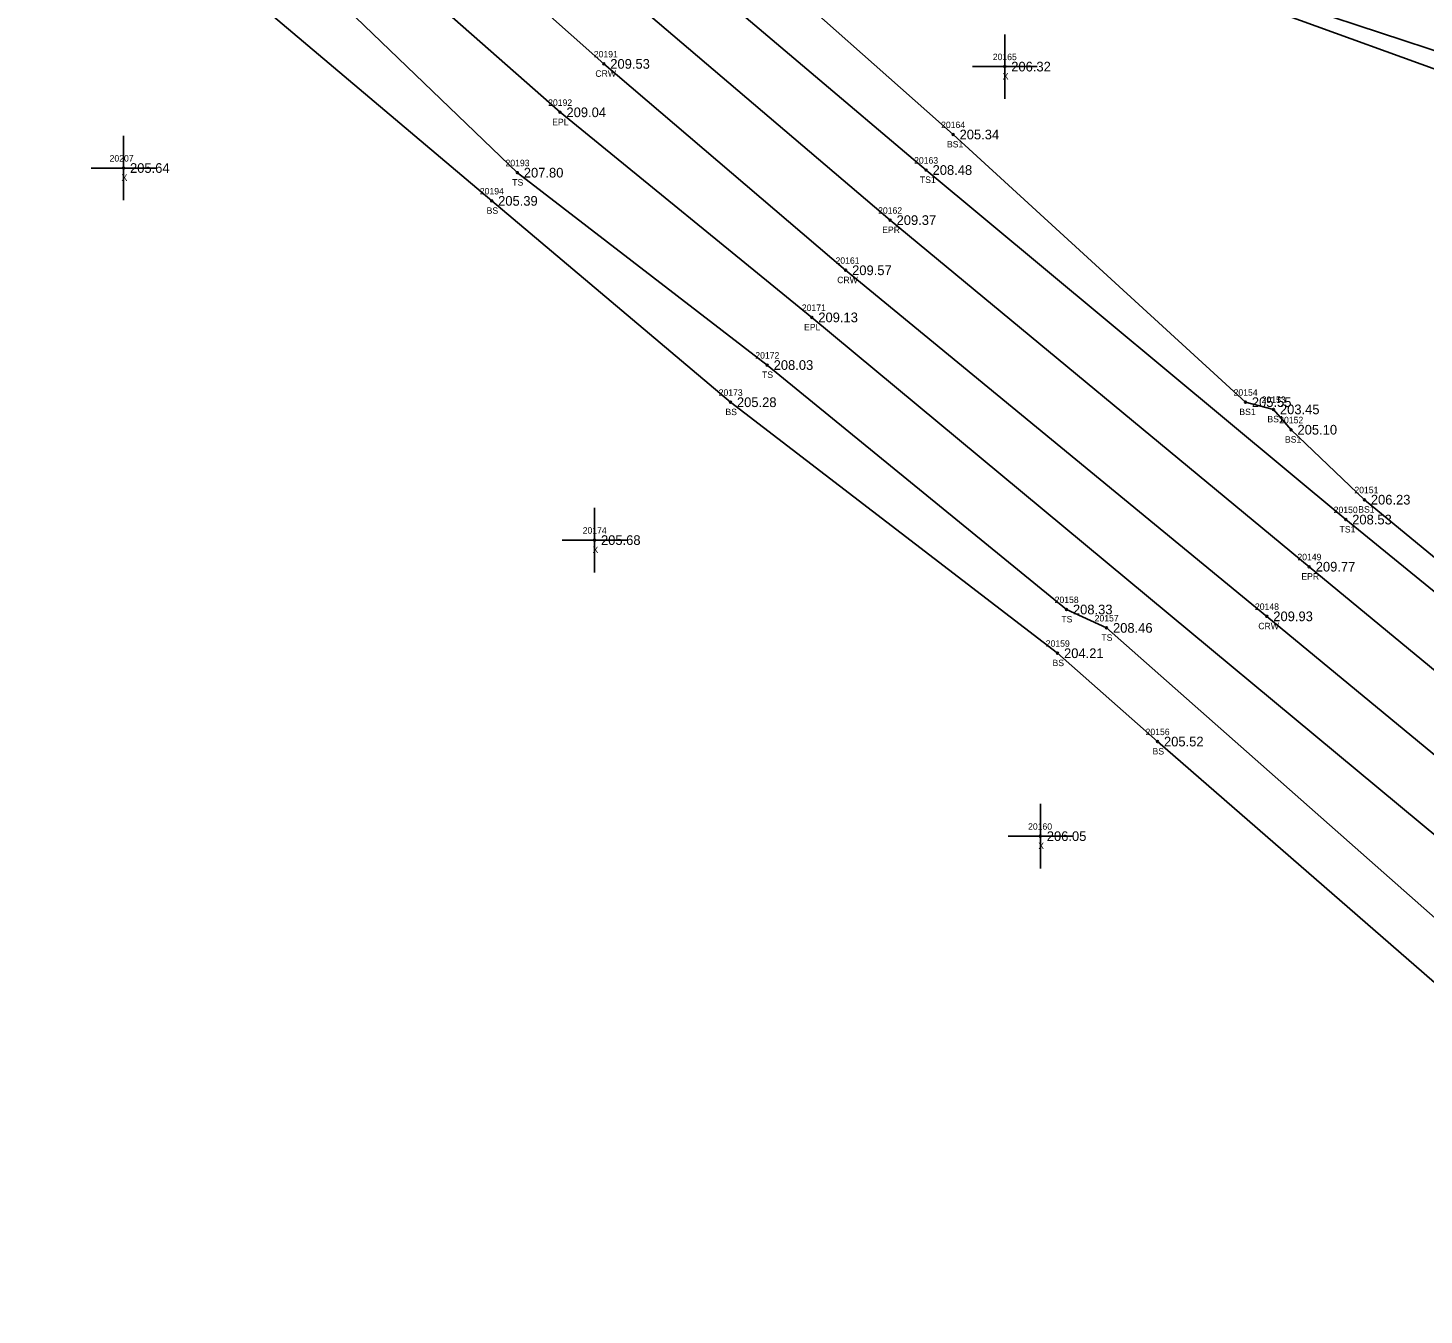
# Model space of a CAD drawing. Extents: x 2260230 to 2261304, y 1064626 to 1065587.
# Drawn here: x 2260481.3 to 2260697.7, y 1065084.2 to 1065283.6 of the extents above; entities that cross this region are included whole.
import ezdxf

# ---------------------------------------------------------------- set-up
doc = ezdxf.new("R2010")
doc.units = 0
for name, color, linetype in [('RD_DTM_BkLn1', 7, 'Continuous'), ('RD_DTM_BkLn2', 7, 'Continuous'), ('RD_DTM_BkLn_txCode', 7, 'Continuous'), ('RD_EX_H2O', 7, 'Continuous'), ('RD_EX_Misc', 7, 'Continuous'), ('RD_EX_Misc_txCode', 7, 'Continuous'), ('RD_EX_Road', 7, 'Continuous'), ('RD_EX_Road_txCode', 7, 'Continuous'), ('RD_EX_TX_Misc_ELEV', 7, 'Continuous'), ('RD_EX_TX_Road_ELEV', 7, 'Continuous'), ('RD_HC_Survey_ELEV', 7, 'Continuous'), ('RD_HC_Survey_txCode', 7, 'Continuous'), ('RD_SMD_Locator', 7, 'Continuous')]:
    doc.layers.add(name, color=color, linetype=linetype)

msp = doc.modelspace()

# ---------------------------------------------------------------- linework, layer by layer
at = {"layer": 'RD_DTM_BkLn1'}
msp.add_lwpolyline([(2260779.46, 1065104.44), (2260742.48, 1065135.39), (2260673.31, 1065192.46), (2260608.04, 1065246.07), (2260570.56, 1065278.04), (2260535.11, 1065309.57), (2260496.97, 1065343.67)], dxfattribs=at)
at = {"layer": 'RD_DTM_BkLn2'}
for points in [[(2260803.42, 1065119.58), (2260791.14, 1065121.96), (2260758.99, 1065152.43), (2260688.43, 1065210.53), (2260677.06, 1065221.37), (2260674.34, 1065224.52), (2260669.99, 1065225.64), (2260624.69, 1065267.1), (2260592.52, 1065295.67), (2260558.99, 1065321.26), (2260536.51, 1065353.04), (2260518.75, 1065355.5), (2260510.38, 1065360.52), (2260499.47, 1065369.14)], [(2260788.43, 1065115.1), (2260756.25, 1065149.85), (2260685.54, 1065207.45), (2260620.51, 1065261.6), (2260582.16, 1065294.05), (2260553.3, 1065320.76), (2260519.6, 1065347.28), (2260508.82, 1065355.88)], [(2260769.94, 1065084.22), (2260759.25, 1065090.93), (2260723.51, 1065114.68), (2260656.37, 1065173.06), (2260640.88, 1065186.75), (2260590.19, 1065225.63), (2260553.18, 1065256.82), (2260516.06, 1065288.21), (2260487.07, 1065314.86), (2260465.96, 1065334.21)], [(2260770.13, 1065093.5), (2260766.75, 1065094.76), (2260758.85, 1065096.78), (2260743.23, 1065112.86), (2260730.88, 1065117.95), (2260648.47, 1065190.67), (2260642.26, 1065193.52), (2260595.88, 1065231.39), (2260557.16, 1065261.19), (2260521.56, 1065295.46), (2260491.43, 1065319.65), (2260484.59, 1065329.16), (2260485.55, 1065330.24)]]:
    msp.add_lwpolyline(points, dxfattribs=at)
at = {"layer": 'RD_EX_H2O'}
for points in [[(2260646.91, 1065297.37), (2260734.94, 1065268.39), (2260788.77, 1065229.77), (2260848.02, 1065204.23), (2260881.52, 1065170.81)], [(2260646.56, 1065296.38), (2260731.62, 1065265.57), (2260787.15, 1065228.1), (2260847.76, 1065200.44), (2260874.83, 1065172.21)]]:
    msp.add_lwpolyline(points, dxfattribs=at)
at = {"layer": 'RD_EX_Misc'}
for p, q in [((2260632.7, 1065272.62), (2260632.7, 1065282.62)), ((2260627.7, 1065277.62), (2260637.7, 1065277.62)), ((2260496.13, 1065256.91), (2260496.13, 1065266.91)), ((2260491.13, 1065261.91), (2260501.13, 1065261.91)), ((2260569.12, 1065199.27), (2260569.12, 1065209.27)), ((2260564.12, 1065204.27), (2260574.12, 1065204.27)), ((2260638.21, 1065153.41), (2260638.21, 1065163.41)), ((2260633.21, 1065158.41), (2260643.21, 1065158.41))]:
    msp.add_line(p, q, dxfattribs=at)
at = {"layer": 'RD_EX_Road'}
for points in [[(2260785.94, 1065112.1), (2260748.83, 1065143.25), (2260679.89, 1065200.15), (2260614.93, 1065253.84), (2260576.4, 1065286.6), (2260541.88, 1065316.4), (2260503.82, 1065350.69)], [(2260773.44, 1065097.37), (2260736.13, 1065128.07), (2260602.8, 1065238.77), (2260563.77, 1065270.54), (2260528.16, 1065301.97), (2260490.72, 1065336.18)]]:
    msp.add_lwpolyline(points, dxfattribs=at)
at = {"layer": 'RD_SMD_Locator'}
for centre in [(2260570.56, 1065278.04), (2260632.7, 1065277.62), (2260563.77, 1065270.54), (2260624.69, 1065267.1), (2260496.13, 1065261.91), (2260557.16, 1065261.19), (2260620.51, 1065261.6), (2260553.18, 1065256.82), (2260614.93, 1065253.84), (2260608.04, 1065246.07), (2260602.8, 1065238.77), (2260595.88, 1065231.39), (2260590.19, 1065225.63), (2260669.99, 1065225.64), (2260674.34, 1065224.52), (2260677.06, 1065221.37), (2260688.43, 1065210.53), (2260685.54, 1065207.45), (2260569.12, 1065204.27), (2260679.89, 1065200.15), (2260642.26, 1065193.52), (2260648.47, 1065190.67), (2260673.31, 1065192.46), (2260640.88, 1065186.75), (2260656.37, 1065173.06), (2260638.21, 1065158.41)]:
    msp.add_circle(centre, 0.15, dxfattribs=at)

# ---------------------------------------------------------------- texts
at = {"layer": 'RD_DTM_BkLn_txCode'}
for s, p in [('20164', (2260622.83, 1065268.1)), ('BS1', (2260623.74, 1065265.1)), ('20193', (2260555.33, 1065262.19)), ('20163', (2260618.65, 1065262.6)), ('TS', (2260556.37, 1065259.19)), ('TS1', (2260619.55, 1065259.6)), ('20194', (2260551.35, 1065257.82)), ('BS', (2260552.4, 1065254.82)), ('20172', (2260594.04, 1065232.39)), ('TS', (2260595.08, 1065229.39)), ('20173', (2260588.36, 1065226.63)), ('20154', (2260668.16, 1065226.64)), ('20153', (2260672.51, 1065225.52)), ('BS', (2260589.41, 1065223.63)), ('BS1', (2260669.05, 1065223.64)), ('BS1', (2260673.4, 1065222.52)), ('20152', (2260675.23, 1065222.37)), ('BS1', (2260676.12, 1065219.37)), ('20151', (2260686.88, 1065211.53)), ('20150', (2260683.67, 1065208.45)), ('BS1', (2260687.48, 1065208.53)), ('TS1', (2260684.58, 1065205.45)), ('20158', (2260640.43, 1065194.52)), ('TS', (2260641.47, 1065191.52)), ('20157', (2260646.63, 1065191.67)), ('20159', (2260639.05, 1065187.75)), ('TS', (2260647.67, 1065188.67)), ('BS', (2260640.1, 1065184.75)), ('20156', (2260654.52, 1065174.06)), ('BS', (2260655.6, 1065171.06))]:
    msp.add_text(s, height=1, dxfattribs=at).set_placement(p)
at = {"layer": 'RD_EX_Misc_txCode'}
for s, p in [('20165', (2260630.84, 1065278.62)), ('X', (2260632.38, 1065275.62)), ('20207', (2260493.97, 1065262.91)), ('X', (2260495.82, 1065259.91)), ('20174', (2260567.29, 1065205.27)), ('X', (2260568.81, 1065202.27)), ('20160', (2260636.31, 1065159.41)), ('X', (2260637.89, 1065156.41))]:
    msp.add_text(s, height=1, dxfattribs=at).set_placement(p)
at = {"layer": 'RD_EX_Road_txCode'}
for s, p in [('20192', (2260561.93, 1065271.54)), ('EPL', (2260562.56, 1065268.54)), ('20162', (2260613.07, 1065254.84)), ('EPR', (2260613.7, 1065251.84)), ('20171', (2260601.25, 1065239.77)), ('EPL', (2260601.59, 1065236.77)), ('20149', (2260678.05, 1065201.15)), ('EPR', (2260678.66, 1065198.15))]:
    msp.add_text(s, height=1, dxfattribs=at).set_placement(p)
at = {"layer": 'RD_EX_TX_Misc_ELEV'}
for s, p in [('206.32', (2260633.7, 1065276.87)), ('205.34', (2260625.69, 1065266.35)), ('205.64', (2260497.13, 1065261.16)), ('207.80', (2260558.16, 1065260.44)), ('208.48', (2260621.51, 1065260.85)), ('205.39', (2260554.18, 1065256.07)), ('208.03', (2260596.88, 1065230.64)), ('205.28', (2260591.19, 1065224.88)), ('205.55', (2260670.99, 1065224.89)), ('203.45', (2260675.34, 1065223.77)), ('205.10', (2260678.06, 1065220.62)), ('206.23', (2260689.43, 1065209.78)), ('208.53', (2260686.54, 1065206.7)), ('205.68', (2260570.12, 1065203.52)), ('208.33', (2260643.26, 1065192.77)), ('208.46', (2260649.47, 1065189.92)), ('204.21', (2260641.88, 1065186)), ('205.52', (2260657.37, 1065172.31)), ('206.05', (2260639.21, 1065157.66))]:
    msp.add_text(s, height=1.5, dxfattribs=at).set_placement(p)
at = {"layer": 'RD_EX_TX_Road_ELEV'}
for s, p in [('209.04', (2260564.77, 1065269.79)), ('209.37', (2260615.93, 1065253.09)), ('209.13', (2260603.8, 1065238.02)), ('209.77', (2260680.89, 1065199.4))]:
    msp.add_text(s, height=1.5, dxfattribs=at).set_placement(p)
at = {"layer": 'RD_HC_Survey_ELEV'}
for s, p in [('209.53', (2260571.56, 1065277.29)), ('209.57', (2260609.04, 1065245.32)), ('209.93', (2260674.31, 1065191.71))]:
    msp.add_text(s, height=1.5, dxfattribs=at).set_placement(p)
at = {"layer": 'RD_HC_Survey_txCode'}
for s, p in [('20191', (2260569.01, 1065279.04)), ('CRW', (2260569.25, 1065276.04)), ('20161', (2260606.47, 1065247.07)), ('CRW', (2260606.73, 1065244.07)), ('20148', (2260671.47, 1065193.46)), ('CRW', (2260671.99, 1065190.46))]:
    msp.add_text(s, height=1, dxfattribs=at).set_placement(p)

doc.saveas('drawing.dxf')
